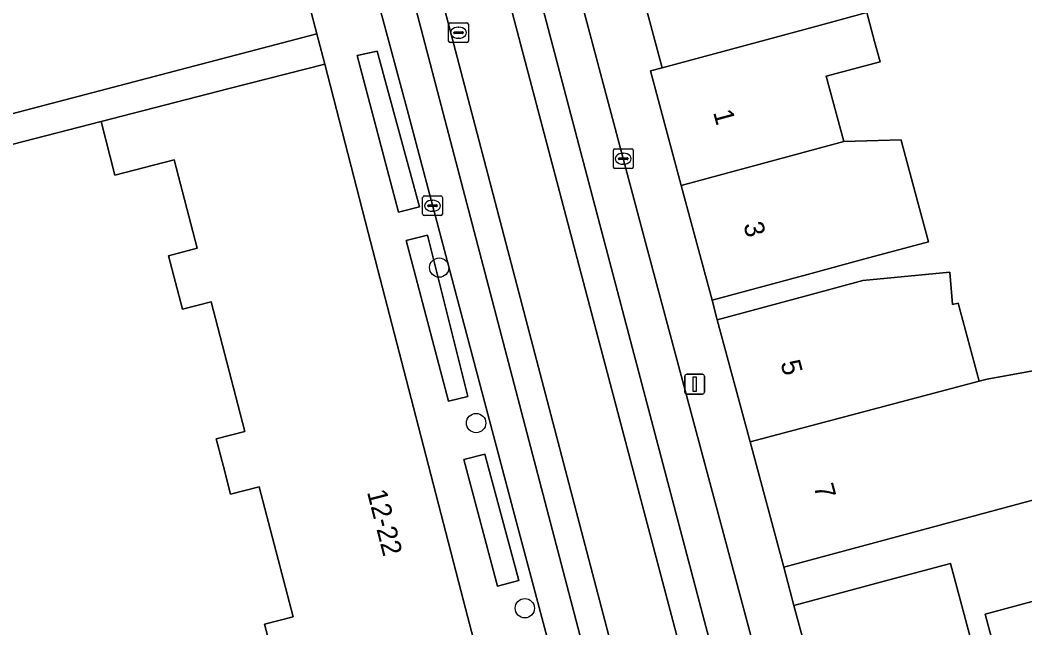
# Model space of a CAD drawing. Extents: x 159371 to 159986, y 382987 to 383597.
# Drawn here: x 159663.3 to 159714.2, y 383358.1 to 383388.8 of the extents above; entities that cross this region are included whole.
import ezdxf

# ---------------------------------------------------------------- set-up
doc = ezdxf.new("R2010")
doc.units = 0
for name, color, linetype in [('IMGEO_Boom', 7, 'Continuous'), ('IMGEO_Erf', 7, 'Continuous'), ('IMGEO_Groenvoorziening', 7, 'Continuous'), ('IMGEO_Kolk', 7, 'Continuous'), ('IMGEO_Lichtmast', 7, 'Continuous'), ('IMGEO_Pand', 7, 'Continuous'), ('IMGEO_Pand_nummerreeks', 7, 'Continuous'), ('IMGEO_Parkeervlak_gesloten', 7, 'Continuous'), ('IMGEO_Rijbaan_lokaal_gesloten', 7, 'Continuous'), ('IMGEO_Rioolput', 7, 'Continuous'), ('IMGEO_Voetpad_open', 7, 'Continuous')]:
    doc.layers.add(name, color=color, linetype=linetype)

msp = doc.modelspace()

# ---------------------------------------------------------------- linework, layer by layer
at = {"layer": 'IMGEO_Boom'}
for centre in [(159684.505, 383376.311), (159686.376, 383368.438), (159688.843, 383359.057)]:
    msp.add_circle(centre, 0.489, dxfattribs=at)
at = {"layer": 'IMGEO_Erf'}
for points in [[(159620.974, 383393.193), (159623.022, 383388.189), (159623.949, 383384.708), (159624.117, 383384.101), (159626.146, 383376.769), (159626.639, 383375.148), (159627.921, 383375.478), (159635.326, 383377.454), (159637.171, 383377.926), (159637.233, 383377.7), (159638.181, 383377.778), (159643.576, 383379.146), (159644.328, 383379.336), (159655.247, 383382.105), (159678.304, 383388.157), (159659.581, 383459.485)], [(159689.89, 383408.493), (159695.793, 383386.432), (159700.622, 383387.732), (159703.447, 383388.493), (159706.168, 383389.226), (159706.561, 383387.767), (159706.838, 383386.738), (159704.111, 383386.004), (159705.003, 383382.691), (159707.903, 383382.782), (159707.943, 383382.633), (159708.62, 383380.119), (159709.293, 383377.62), (159706.075, 383376.754), (159703.155, 383375.968), (159698.326, 383374.668), (159698.591, 383373.663), (159703.42, 383374.963), (159705.971, 383375.65), (159710.377, 383376.086), (159710.513, 383374.438), (159710.788, 383374.507), (159711.852, 383370.554), (159712.266, 383370.665), (159724.21, 383372.844)], [(159676.002, 383356.895), (159675.649, 383358.25), (159677.101, 383358.628), (159675.39, 383365.21), (159673.938, 383364.832), (159673.573, 383366.235), (159673.208, 383367.638), (159674.66, 383368.016), (159672.954, 383374.578), (159671.502, 383374.2), (159671.149, 383375.555), (159670.797, 383376.91), (159672.249, 383377.288), (159671.084, 383381.762), (159668.082, 383380.988), (159667.381, 383383.709), (159657.266, 383381.105)], [(159719.014, 383365.734), (159706.791, 383362.443), (159701.962, 383361.143), (159702.478, 383359.191), (159707.306, 383360.492), (159710.4, 383361.325), (159711.489, 383357.283), (159712.485, 383357.551), (159712.159, 383358.763), (159720.808, 383361.092)]]:
    msp.add_lwpolyline(points, dxfattribs=at)
at = {"layer": 'IMGEO_Groenvoorziening'}
for points in [[(159680.353, 383387.048), (159682.448, 383379.122), (159683.508, 383379.394), (159681.357, 383387.273)], [(159682.83, 383377.678), (159684.982, 383369.537), (159685.96, 383369.786), (159683.908, 383377.946)], [(159685.761, 383366.59), (159687.458, 383360.172), (159688.538, 383360.461), (159686.817, 383366.86)]]:
    msp.add_lwpolyline(points, close=True, dxfattribs=at)
at = {"layer": 'IMGEO_Kolk'}
for p, q in [((159693.327, 383381.402), (159693.327, 383382.254)), ((159693.402, 383382.328), (159694.254, 383382.328)), ((159693.815, 383382.108), (159693.84, 383382.108)), ((159694.328, 383382.254), (159694.328, 383381.402)), ((159693.586, 383381.822), (159693.586, 383381.834)), ((159694.024, 383381.785), (159693.626, 383381.785)), ((159693.629, 383381.871), (159694.027, 383381.871)), ((159693.838, 383381.548), (159693.813, 383381.548)), ((159694.07, 383381.834), (159694.07, 383381.822)), ((159694.254, 383381.328), (159693.402, 383381.328)), ((159683.668, 383379.017), (159683.668, 383379.869)), ((159683.743, 383379.943), (159684.595, 383379.943)), ((159684.669, 383379.869), (159684.669, 383379.017)), ((159683.927, 383379.437), (159683.927, 383379.449)), ((159684.365, 383379.4), (159683.967, 383379.4)), ((159683.97, 383379.486), (159684.368, 383379.486)), ((159684.156, 383379.723), (159684.181, 383379.723)), ((159684.411, 383379.449), (159684.411, 383379.437)), ((159684.595, 383378.943), (159683.743, 383378.943)), ((159684.179, 383379.163), (159684.154, 383379.163))]:
    msp.add_line(p, q, dxfattribs=at)
for points in [[(159693.327, 383381.402), (159693.327, 383382.254)], [(159693.402, 383382.328), (159694.254, 383382.328)], [(159694.328, 383382.254), (159694.328, 383381.402)], [(159694.254, 383381.328), (159693.402, 383381.328)], [(159683.668, 383379.017), (159683.668, 383379.869)], [(159683.743, 383379.943), (159684.595, 383379.943)], [(159684.669, 383379.869), (159684.669, 383379.017)], [(159684.595, 383378.943), (159683.743, 383378.943)]]:
    msp.add_lwpolyline(points, dxfattribs=at)
for centre, radius, start, end in [((159693.404, 383382.252), 0.0765, 91.552, 178.448), ((159693.404, 383382.252), 0.0765, 91.552, 178.448), ((159694.252, 383382.252), 0.0765, 1.552, 88.448), ((159694.252, 383382.252), 0.0765, 1.552, 88.448), ((159693.404, 383381.404), 0.0765, 181.552, 268.448), ((159693.404, 383381.404), 0.0765, 181.552, 268.448), ((159693.626, 383381.831), 0.0403, 85.8775, 175.7526), ((159693.623, 383381.821), 0.0366, 178.938, 274.7102), ((159694.027, 383381.828), 0.043, 264.8664, 352.4533), ((159694.031, 383381.833), 0.0386, 1.7309, 96.639), ((159694.252, 383381.404), 0.0765, 271.552, 358.448), ((159694.252, 383381.404), 0.0765, 271.552, 358.448), ((159683.745, 383379.867), 0.0765, 91.552, 178.448), ((159683.745, 383379.867), 0.0765, 91.552, 178.448), ((159684.593, 383379.867), 0.0765, 1.552, 88.448), ((159684.593, 383379.867), 0.0765, 1.552, 88.448), ((159683.967, 383379.446), 0.0403, 85.8775, 175.7526), ((159683.964, 383379.436), 0.0366, 178.938, 274.7102), ((159684.368, 383379.443), 0.043, 264.8664, 352.4533), ((159684.372, 383379.448), 0.0386, 1.7309, 96.639), ((159683.745, 383379.019), 0.0765, 181.552, 268.448), ((159683.745, 383379.019), 0.0765, 181.552, 268.448), ((159684.593, 383379.019), 0.0765, 271.552, 358.448), ((159684.593, 383379.019), 0.0765, 271.552, 358.448)]:
    msp.add_arc(centre, radius, start, end, dxfattribs=at)
for centre, major_axis, ratio, start_param, end_param in [((159693.814, 383381.828), (-0.387, 0.002), 0.722429, 4.712389, 7.853982), ((159693.839, 383381.828), (-0.39, 0.002), 0.717154, 1.570796, 4.712389), ((159684.155, 383379.443), (-0.387, 0.002), 0.722429, 4.712389, 7.853982), ((159684.18, 383379.443), (-0.39, 0.002), 0.717154, 1.570796, 4.712389)]:
    msp.add_ellipse(centre, major_axis=major_axis, ratio=ratio, start_param=start_param, end_param=end_param, dxfattribs=at)
at = {"layer": 'IMGEO_Lichtmast'}
for p, q in [((159696.948, 383370.006), (159696.948, 383370.806)), ((159696.948, 383370.806), (159696.948, 383370.006)), ((159697.048, 383370.906), (159697.838, 383370.906)), ((159697.838, 383370.906), (159697.048, 383370.906)), ((159697.938, 383370.806), (159697.938, 383370.006)), ((159697.938, 383370.006), (159697.938, 383370.806)), ((159697.838, 383369.906), (159697.048, 383369.906)), ((159697.048, 383369.906), (159697.838, 383369.906))]:
    msp.add_line(p, q, dxfattribs=at)
msp.add_lwpolyline([(159697.368, 383370.781), (159697.518, 383370.781), (159697.518, 383370.031), (159697.368, 383370.031), (159697.368, 383370.781)], dxfattribs=at)
for centre, start, end in [((159697.048, 383370.806), 90, 180), ((159697.048, 383370.806), 90, 180), ((159697.838, 383370.806), 0, 90), ((159697.838, 383370.806), 360, 90), ((159697.048, 383370.006), 180, 270), ((159697.048, 383370.006), 180, 270), ((159697.838, 383370.006), 270, 0), ((159697.838, 383370.006), 270, 0)]:
    msp.add_arc(centre, 0.1, start, end, dxfattribs=at)
at = {"layer": 'IMGEO_Pand'}
for points in [[(159704.111, 383386.004), (159706.838, 383386.738), (159706.561, 383387.767), (159706.168, 383389.226), (159703.447, 383388.493), (159700.622, 383387.732), (159695.793, 383386.432), (159695.202, 383386.273), (159696.764, 383380.472), (159705.003, 383382.691)], [(159705.003, 383382.691), (159696.764, 383380.472), (159698.326, 383374.668), (159703.155, 383375.968), (159706.075, 383376.754), (159709.293, 383377.62), (159708.62, 383380.119), (159707.943, 383382.633), (159707.903, 383382.782)], [(159710.788, 383374.507), (159710.513, 383374.438), (159710.377, 383376.086), (159705.971, 383375.65), (159703.42, 383374.963), (159698.591, 383373.663), (159700.256, 383367.478), (159711.852, 383370.554)], [(159724.21, 383372.844), (159712.266, 383370.665), (159711.852, 383370.554), (159700.256, 383367.478), (159701.962, 383361.143), (159706.791, 383362.443), (159719.014, 383365.734), (159723.85, 383367.036), (159725.412, 383367.457), (159726.361, 383367.712), (159726.507, 383367.751), (159726.661, 383367.793), (159724.943, 383372.978)], [(159720.808, 383361.092), (159712.159, 383358.763), (159712.485, 383357.551), (159711.489, 383357.283), (159710.4, 383361.325), (159707.306, 383360.492), (159702.478, 383359.191), (159704.034, 383353.41), (159717.318, 383356.983), (159721.603, 383358.136)]]:
    msp.add_lwpolyline(points, close=True, dxfattribs=at)
msp.add_lwpolyline([(159686.767, 383355.473), (159685.743, 383359.431), (159683.326, 383368.772), (159680.913, 383378.095), (159678.706, 383386.624), (159673.864, 383385.378), (159667.381, 383383.709), (159668.082, 383380.988), (159671.084, 383381.762), (159672.249, 383377.288), (159670.797, 383376.91), (159671.149, 383375.555), (159671.502, 383374.2), (159672.954, 383374.578), (159674.66, 383368.016), (159673.208, 383367.638), (159673.573, 383366.235), (159673.938, 383364.832), (159675.39, 383365.21), (159677.101, 383358.628), (159675.649, 383358.25), (159676.002, 383356.895)], dxfattribs=at)
at = {"layer": 'IMGEO_Parkeervlak_gesloten'}
for points in [[(159690.128, 383395.731), (159689.221, 383399.138), (159688.963, 383400.109), (159679.139, 383437.543), (159674.718, 383453.996), (159673.929, 383456.929), (159673.465, 383458.741), (159672.103, 383458.409), (159671.763, 383458.326), (159671.587, 383458.28), (159673.093, 383452.571), (159675.902, 383441.929), (159681.054, 383422.407), (159689.359, 383390.944), (159696.414, 383364.212), (159703.844, 383336.06), (159706.907, 383324.871), (159707.101, 383324.923)], [(159665.691, 383456.728), (159663.864, 383456.282), (159664.964, 383452.218), (159665.106, 383451.555), (159670.1, 383433.187), (159678.787, 383399.561), (159682.877, 383384.322), (159688.475, 383363.216), (159690.31, 383356.311), (159696.363, 383333.532), (159698.5, 383325.536), (159698.524, 383325.331)], [(159700.731, 383323.191), (159691.898, 383356.687), (159665.691, 383456.728)], [(159707.981, 383328.527), (159707.905, 383328.707), (159707.718, 383329.61), (159707.422, 383330.754), (159707.334, 383331.079), (159706.48, 383334.224), (159705.825, 383336.598), (159702.961, 383347.681), (159700.034, 383358.613), (159695.004, 383377.404), (159690.128, 383395.731)]]:
    msp.add_lwpolyline(points, dxfattribs=at)
at = {"layer": 'IMGEO_Rijbaan_lokaal_gesloten'}
for points in [[(159671.587, 383458.28), (159670.74, 383458.056), (159670.094, 383457.885), (159670.625, 383455.872), (159678.409, 383426.38), (159686.465, 383395.857), (159692.786, 383371.909), (159698.534, 383350.133), (159705.315, 383324.44), (159706.001, 383324.626), (159706.907, 383324.871), (159703.844, 383336.06), (159696.414, 383364.212), (159689.359, 383390.944), (159681.054, 383422.407), (159675.902, 383441.929), (159673.093, 383452.571)], [(159665.933, 383456.787), (159665.691, 383456.728), (159691.898, 383356.687), (159700.731, 383323.191), (159702.049, 383323.57), (159696.447, 383345.036), (159693.274, 383357.013), (159667.185, 383456.552), (159667.027, 383457.076)]]:
    msp.add_lwpolyline(points, close=True, dxfattribs=at)
msp.add_lwpolyline([(159710.058, 383306.882), (159710.001, 383307.233), (159707.101, 383324.923), (159706.907, 383324.871), (159706.001, 383324.626), (159705.315, 383324.44), (159698.534, 383350.133), (159692.786, 383371.909), (159686.465, 383395.857), (159678.409, 383426.38), (159670.625, 383455.872), (159670.094, 383457.885), (159667.027, 383457.076), (159667.185, 383456.552), (159693.274, 383357.013), (159696.447, 383345.036), (159702.049, 383323.57), (159700.731, 383323.191)], dxfattribs=at)
at = {"layer": 'IMGEO_Rioolput'}
for p, q in [((159684.983, 383387.783), (159684.983, 383388.635)), ((159685.058, 383388.709), (159685.91, 383388.709)), ((159685.984, 383388.635), (159685.984, 383387.783)), ((159685.242, 383388.203), (159685.242, 383388.215)), ((159685.68, 383388.166), (159685.282, 383388.166)), ((159685.285, 383388.252), (159685.683, 383388.252)), ((159685.471, 383388.489), (159685.496, 383388.489)), ((159685.726, 383388.215), (159685.726, 383388.203)), ((159685.91, 383387.709), (159685.058, 383387.709)), ((159685.494, 383387.929), (159685.469, 383387.929))]:
    msp.add_line(p, q, dxfattribs=at)
for points in [[(159684.983, 383387.783), (159684.983, 383388.635)], [(159685.058, 383388.709), (159685.91, 383388.709)], [(159685.984, 383388.635), (159685.984, 383387.783)], [(159685.91, 383387.709), (159685.058, 383387.709)]]:
    msp.add_lwpolyline(points, dxfattribs=at)
for centre, radius, start, end in [((159685.06, 383388.633), 0.0765, 91.552, 178.448), ((159685.06, 383388.633), 0.0765, 91.552, 178.448), ((159685.908, 383388.633), 0.0765, 1.552, 88.448), ((159685.908, 383388.633), 0.0765, 1.552, 88.448), ((159685.282, 383388.212), 0.0403, 85.8775, 175.7526), ((159685.279, 383388.202), 0.0366, 178.938, 274.7102), ((159685.683, 383388.209), 0.043, 264.8664, 352.4533), ((159685.687, 383388.214), 0.0386, 1.7309, 96.639), ((159685.06, 383387.785), 0.0765, 181.552, 268.448), ((159685.06, 383387.785), 0.0765, 181.552, 268.448), ((159685.908, 383387.785), 0.0765, 271.552, 358.448), ((159685.908, 383387.785), 0.0765, 271.552, 358.448)]:
    msp.add_arc(centre, radius, start, end, dxfattribs=at)
for centre, major_axis, ratio, start_param, end_param in [((159685.47, 383388.209), (-0.387, 0.002), 0.722429, 4.712389, 7.853982), ((159685.495, 383388.209), (-0.39, 0.002), 0.717154, 1.570796, 4.712389)]:
    msp.add_ellipse(centre, major_axis=major_axis, ratio=ratio, start_param=start_param, end_param=end_param, dxfattribs=at)
at = {"layer": 'IMGEO_Voetpad_open'}
for points in [[(159658.393, 383463.518), (159659.066, 383461.404), (159659.581, 383459.485), (159678.304, 383388.157), (159678.706, 383386.624), (159680.913, 383378.095), (159683.326, 383368.772), (159685.743, 383359.431), (159686.767, 383355.473), (159688.157, 383350.102), (159690.86, 383339.654), (159691.725, 383332.764), (159695.046, 383323.244), (159698.94, 383324.722)], [(159713.918, 383320.127), (159711.636, 383324.71), (159710.541, 383328.856), (159709.903, 383331.579), (159708.979, 383335.062), (159707.422, 383340.842), (159705.865, 383346.625), (159705.59, 383347.631), (159704.034, 383353.41), (159702.478, 383359.191), (159701.962, 383361.143), (159700.256, 383367.478), (159698.591, 383373.663), (159698.326, 383374.668), (159696.764, 383380.472), (159695.202, 383386.273), (159695.793, 383386.432), (159689.89, 383408.493), (159681.184, 383441.029)], [(159698.524, 383325.331), (159698.5, 383325.536), (159696.363, 383333.532), (159690.31, 383356.311), (159688.475, 383363.216), (159682.877, 383384.322), (159678.787, 383399.561)], [(159690.128, 383395.731), (159695.004, 383377.404), (159700.034, 383358.613), (159702.961, 383347.681), (159705.825, 383336.598), (159706.48, 383334.224), (159707.481, 383334.478), (159708.477, 383331.026), (159707.422, 383330.754), (159707.718, 383329.61), (159707.905, 383328.707), (159707.981, 383328.527)], [(159657.266, 383381.105), (159667.381, 383383.709), (159673.864, 383385.378), (159678.706, 383386.624), (159678.304, 383388.157), (159655.247, 383382.105)]]:
    msp.add_lwpolyline(points, dxfattribs=at)
for points in [[(159681.357, 383387.273), (159683.508, 383379.394), (159682.448, 383379.122), (159680.353, 383387.048)], [(159683.908, 383377.946), (159685.96, 383369.786), (159684.982, 383369.537), (159682.83, 383377.678)], [(159686.817, 383366.86), (159688.538, 383360.461), (159687.458, 383360.172), (159685.761, 383366.59)]]:
    msp.add_lwpolyline(points, close=True, dxfattribs=at)

# ---------------------------------------------------------------- texts
at = {"layer": 'IMGEO_Pand_nummerreeks'}
for s, rotation, p in [('1', 285.0686, (159698.375, 383384.184)), ('3', 285.0628, (159699.907, 383378.491)), ('5', 285.0686, (159701.786, 383371.491)), ('7', 285.0743, (159703.471, 383365.232)), ('12-22', 284.3753, (159680.841, 383364.945))]:
    msp.add_text(s, height=1, rotation=rotation, dxfattribs=at).set_placement(p)

doc.saveas('drawing.dxf')
